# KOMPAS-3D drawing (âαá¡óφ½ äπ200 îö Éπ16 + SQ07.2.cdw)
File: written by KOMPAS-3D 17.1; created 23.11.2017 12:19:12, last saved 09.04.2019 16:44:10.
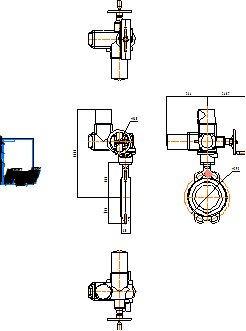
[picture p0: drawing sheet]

Sheet 1: A4, portrait

Title block, sheet 1: name: Гранвэл Ду200 МФ Ру16 + / SQ07.2; material: Внимание! Данный продукт является объектом авторского права ООО «Торговый Дом АДЛ». / Запрещается изменение, копирование, распространение / (в том числе путем копирования на другие сайты и ресурсы в Интернете) / или любое иное использование информации и объектов без предварительного / согласия правообладателя (ООО «Торговый Дом АДЛ»).; mass: 94; sheets: 1; organisation: ООО "Торговый дом АДЛ"; sheet format: A4; stored path: \\adlc.lan\data\АДЛ_ПКД\3D-модели\ADL production\Дисковые поворотные затворы ГРАНВЭЛ\межфланцевый с эл.приводом Auma Ру 16\KOMPAS 2D\Гранвэл Ду200 МФ Ру16 + SQ07.2.cdw

Views: Вид 1, Проекционный вид 4, Проекционный вид 5
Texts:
  kka
  adl
Dimensions and other numbers on the sheet: 160; 60; 225; 170; 568,5; 1:1; 1; 94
